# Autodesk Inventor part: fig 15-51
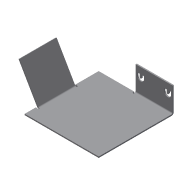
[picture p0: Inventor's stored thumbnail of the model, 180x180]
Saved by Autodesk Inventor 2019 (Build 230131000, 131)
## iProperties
Shininess: 77.0
Angle Display Precision: 2
Document Length Units: 11269
Document Angle Units: 11279
Document Time Units: 11290
Document Mass Units: 11283
Document Length Units Precision: 3
Document Angle Units Precision: 2
Created: 2002-04
Part Number: fig 15-51
Document SubType Name: Sheet Metal
Density: 1 g/cm^3
Sheet Metal Rule: Default
Material: Generic
Appearance: Default
Density: 0.0
Volumn: 0.0
Area: 0.0
PropertySet Name: Model Information
Control State: 0
Master: False
Checked Out: False
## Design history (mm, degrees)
node "Face1"
  sketch "Sketch1"
    geometry: L1 (12.647, 25.882)-(12.647, -14.118); L2 (12.647, -14.118)-(-17.353, -14.118); L3 (-17.353, -14.118)-(-17.353, 15.882); L4 (-17.353, 15.882)-(-2.353, 15.882); L5 (-2.353, 15.882)-(-2.353, 25.882); L6 (-2.353, 25.882)-(12.647, 25.882); 1 further point
    constraints: 12 end point, 4 parallel, 1 perpendicular
    dimensions: "d5" = 30 distance of L2.end L3.end; "d6" = 10 distance of L4.end L5.end; "d7" = 15 distance of L3.end L4.end; "d25" = 15 distance of L5.end L1.start
sketch "Sketch3"
  geometry: L1 (10, -15)-(10, 0)
  constraints: 2 end point
feature "Fold3" sketch "Sketch3" dims "d26" = 0.5 (= BendRadius), "d27" = 90 deg, "d28" = 0.5 (= BendRadius), "d96" = 0.5 (= BendReliefWidth), "d97" = 0.25 (= BendReliefDepth), "d98" = 1 (= MinimumRemnant), "d107" = 0.5 (= Thickness), "SeamGap" = 0.01
node "Flange2"
sketch "Sketch6"
  geometry: L1 (-6.914, 3.413)-(-5.843, 3.413); L2 (-5.843, 0.624)-(-6.914, 0.624); L3 (-6.914, 2.432)-(-5.843, 2.432); L4 (-5.843, 1.605)-(-6.914, 1.605); L5 (-6.914, 0.624)-(-6.914, 1.605); L6 (-6.914, 2.432)-(-6.914, 3.413); L7 (-6.914, 12.568)-(-6.914, 11.587); L8 (-6.914, 14.376)-(-6.914, 13.395); L9 (-6.914, 11.587)-(-5.843, 11.587); L10 (-5.843, 14.376)-(-6.914, 14.376); L11 (-6.914, 12.568)-(-5.843, 12.568); L12 (-5.843, 13.395)-(-6.914, 13.395); A1 r 1.394 centre (-5.843, 2.018) between (-5.843, 0.624) and (-5.843, 3.413); A2 r 0.413 centre (-5.843, 2.018) between (-5.843, 1.605) and (-5.843, 2.432); A3 r 1.394 centre (-5.843, 12.982) between (-5.843, 11.587) and (-5.843, 14.376); A4 r 0.413 centre (-5.843, 12.982) between (-5.843, 12.568) and (-5.843, 13.395)
  constraints: 24 end point, 8 point on circle, 4 centre point, 3 equal length, 1 perpendicular
cut "Cut1" sketch "Sketch6" dims "d49" = 0.5 (= Thickness), "d50" = 0
body "Solid1"
face "Plate1" dims "d107" = 0.5 (= Thickness)
sketch "Sketch5"
  geometry: L1 (20, 0)-(5, 0); L2 (5, 0)-(5, 15); L3 (5, 15)-(20, 15); L4 (20, 15)-(20, 0)
  constraints: 8 end point
face "Plate6" dims "d35" = 10, "d36" = 5, "d38" = 15, "d39" = 60 deg, "d40" = 0.5 (= BendRadius), "d107" = 0.5 (= Thickness), "MinimumRemnant" = 1 (= 2 x Thickness), "BendReliefWidth" = 0.5 (= Thickness)
bend "Bend5" dims "d38" = 15, "d39" = 60 deg, "d40" = 0.5 (= BendRadius), "d99" = 0.5 (= BendReliefWidth), "d100" = 0.25 (= BendReliefDepth), "d101" = 1 (= MinimumRemnant), "d107" = 0.5 (= Thickness), "SeamGap" = 0.01, "MinimumRemnant" = 1 (= 2 x Thickness), "BendReliefWidth" = 0.5 (= Thickness), "TransitionRadius" = 0.5 (= BendRadius)
other parameters: "Thickness" = 0.5, "BendRadius" = 0.5 (= Thickness), "BendReliefDepth" = 0.25 (= 0.5 x Thickness), "CornerReliefSize" = 2 (= 4 x Thickness), "d0" = 0.5 (= BendRadius), "d13" = 0.5 (= BendRadius), "d31" = 0.5 (= BendRadius), "d37" = 0.5 (= BendRadius), "JacobiRadiusSize" = 0.5 (= Thickness), "GapSize" = 0.5 (= Thickness)
